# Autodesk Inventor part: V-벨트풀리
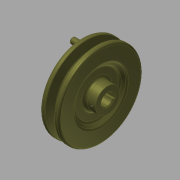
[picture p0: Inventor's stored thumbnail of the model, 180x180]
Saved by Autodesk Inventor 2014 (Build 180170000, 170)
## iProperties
Company: 한국ATC센터
Created: 2015-12
Part Number: V-벨트풀리
Document SubType Name: Modeling
Designer: mdu
Density: 7.25 g/cm^3
Mass: 596.621 g
Surface Area: 212.231 cm^2
Volume: 82.2926 cm^3
Material: 주철
Appearance: 티타늄
Author: mdu
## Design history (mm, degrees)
sketch "스케치1"
  geometry: L1 (-13, 0)-(13, 0); L2 (-13, 0)-(-13, 12.5); L3 (-13, 12.5)-(-9, 12.5); L4 (-9, 12.5)-(-9, 23); L5 (-9, 23)-(-13, 27); L6 (-13, 27)-(-13, 42.7); L7 (-13, 42.7)-(-8.325, 42.7); L8 (-8.325, 42.7)-(-5.574, 33.7); L9 (-5.574, 33.7)-(-1.426, 33.7); L10 (-1.426, 33.7)-(1.325, 42.7); L11 (1.325, 42.7)-(6, 42.7); L12 (6, 42.7)-(6, 27); L13 (6, 27)-(2, 23); L14 (2, 23)-(2, 12.5); L15 (2, 12.5)-(13, 12.5); L16 (13, 12.5)-(13, 0); L17 (-7.5, 40)-(0.5, 40); 2 further points
  constraints: 34 end point, 6 parallel, 5 collinear, 5 equal length, 4 perpendicular, 2 point on line, 1 coincident, 1 horizontal, 1 midpoint
  dimensions: "d0" = 26 distance of L1.start L1.end; "d1" = 2.7 distance between parallel lines of L7 L17; "d2" = 6.3 distance between parallel lines of L9 L17; "d3" = 8 distance of L17.start L17.end; "d4" = 34 deg angle of L10 L8; "d5" = 19 distance between parallel lines of L12 L6; "d7" = 25 diameter of L15 L1; "d8" = 46 diameter of L13.end L1; "d9" = 54 diameter of L12.end L1; "d10" = 4 distance between parallel lines of L2 L4; "d11" = 80 diameter of L17 L1
revolve "회전1" sketch "스케치1" stored, may be unused: angle "d12" = 90 deg
sketch "스케치2"
  geometry: L1 (-2, 5.657)-(-2, 7.8); L2 (-2, 7.8)-(2, 7.8); L3 (2, 7.8)-(2, 5.657); A1 r 6 centre (0, 0) between (-2, 5.657) and (2, 5.657); 1 further point
  constraints: 6 end point, 2 parallel, 2 point on circle, 1 centre point, 1 coincident, 1 perpendicular, 1 vertical
  dimensions: "d13" = 12 diameter of A1; "d14" = 13.8 dimension on A1 L2; "d15" = 4 distance of L1.end L2.end
extrude "돌출1" cut sketch "스케치2" stored distance "d16" = 10; taper "d17" = 0 deg
node "작업 평면1"
sketch "스케치3"
  geometry: L1 (-5.5, 12.5)-(-5.5, -12.5) reference; L2 (20.5, 27)-(20.5, -27) reference; 3 further points
  constraints: 1 horizontal alignment, 1 midpoint
  dimensions: "d18" = 4 distance from line of point (-1.5, 0) L1; "d33" = 22 distance from line of point (-1.5, 0) L2 (derived)
hole "구멍1" sketch "스케치3" at (-1.5, 0) diameter "d19" = 2.459; stored, may be unused: countersink angle "d23" = 90 deg, drill point angle "d25" = 118 deg; dims "d20" = 6, "d21" = 4, "d22" = 2, "d24" = 8
fillet "모깎기1" dims "d26" = 2, "d27" = 0.5, "d28" = 1, "d29" = 3
chamfer "모따기1" distance "d30" = 1; stored, may be unused: second distance "d31" = 2, angle "d32" = 45 deg
sketch "스케치4" dims "d35" = 70
  geometry: C1 r 3 at (35, 0); 2 further points
  constraints: 2 horizontal alignment, 1 centre point, 1 coincident, 2 other
  dimensions: "d34" = 6 diameter of C1
extrude "돌출2" join sketch "스케치4" distance "d36" = 10; taper "d37" = 0 deg
fillet "모깎기2" dims "d38" = 0.5, "d39" = 1
node "솔리드1"
